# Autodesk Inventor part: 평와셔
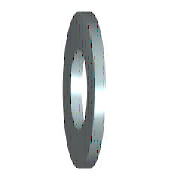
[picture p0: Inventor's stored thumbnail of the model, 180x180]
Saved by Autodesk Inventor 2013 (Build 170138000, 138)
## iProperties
Created: 2012-02
Part Number: 평와셔
Material: 강철
Description: 평면 와셔 - 초대형 시리즈 - 제품 등급 C
Document SubType Name: Modeling
Standard: ISO 7094
Designer: mduedu
Standard Revision: Second edition 2000-06-01
Standards Organization: ISO
Language: ko-KR
Size Designation: ST 5 - 100 HV
Categories: <MemberInstance><Categories><Category DisplayName="조임쇠" InternalName="e4da775c-781d-43d5-af7c-5136215cf5a6" Mnemonic="FSTN"><Category DisplayName="와셔" InternalN
Density: 7.85 g/cm^3
IsCustomPart: 1
Author: mduedu
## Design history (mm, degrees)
sketch "스케치"
  geometry: C1 r 9 at (0, 0); C2 r 2.75 at (0, 0); 1 further point
  constraints: 2 centre point, 2 coincident
  dimensions: "d0" = 5.5 diameter of C2 (= SD1); "d1" = 18 diameter of C1 (= SD2)
extrude "본체" new body sketch "스케치" distance "d2" = 2 (= SD); taper "d3" = 0 deg
workaxis "Work Axis1"
workplane "Work Plane1"
body "Solid1"
other parameters: "SD1" = 5.5 [user parameter; used in 1 equation term], "SD2" = 18 [user parameter; used in 1 equation term], "SD" = 2 [user parameter; used in 1 equation term], "d4" = 0, "d5" = 0, "d6" = 0, "d7" = 0, "NND" = 5 [user parameter]
